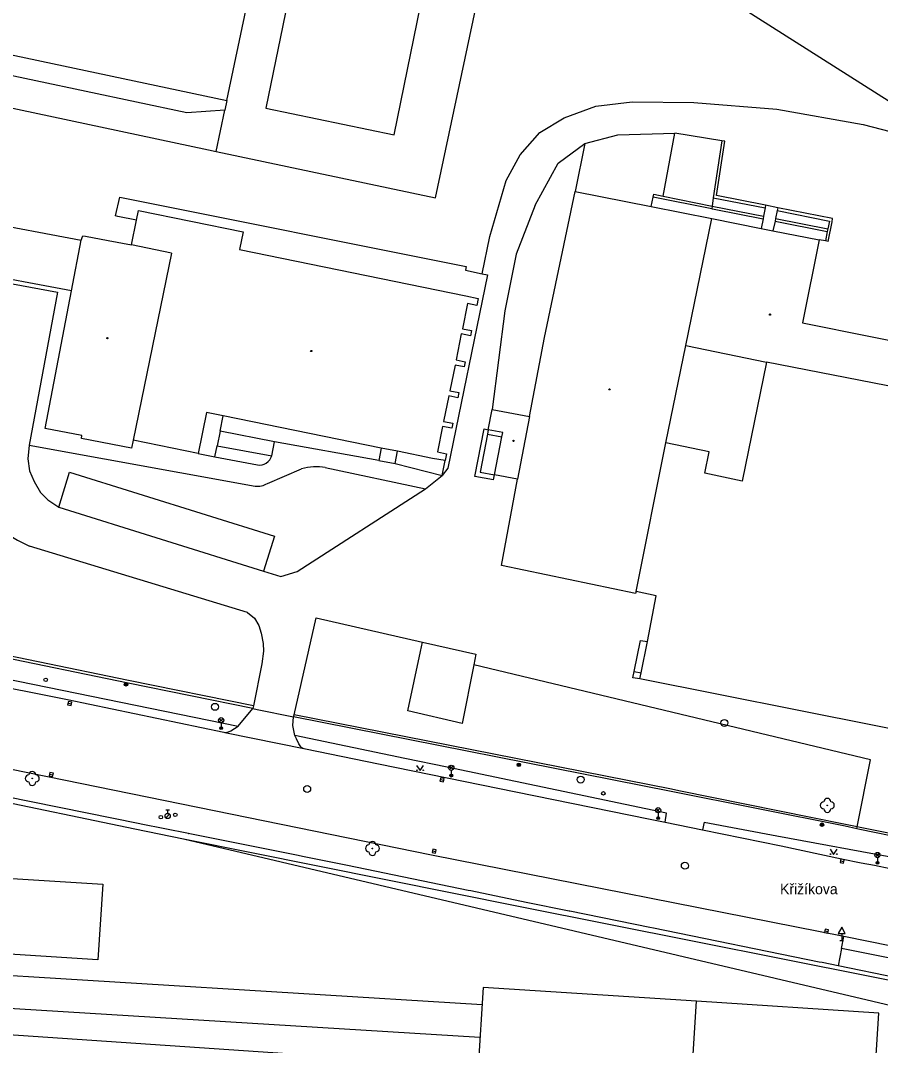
# Model space of a CAD drawing. Extents: x -598233 to -596890, y -1157848 to -1156431.
# Drawn here: x -597625.8 to -597502.6, y -1157653.8 to -1157507 of the extents above; entities that cross this region are included whole.
import ezdxf

# ---------------------------------------------------------------- set-up
doc = ezdxf.new("R2010")
doc.units = 0
for name, color, linetype in [('Level 10', 7, 'Continuous'), ('Level 11', 7, 'Continuous'), ('Level 13', 7, 'Continuous'), ('Level 22', 7, 'Continuous'), ('Level 25', 7, 'Continuous'), ('Level 27', 7, 'Continuous'), ('Level 28', 7, 'Continuous'), ('Level 33', 7, 'Continuous'), ('Level 34', 7, 'Continuous'), ('Level 36', 7, 'Continuous'), ('Level 39', 7, 'Continuous'), ('Level 49', 7, 'Continuous'), ('Level 5', 7, 'Continuous'), ('Level 51', 7, 'Continuous'), ('Level 7', 7, 'Continuous'), ('Level 8', 7, 'Continuous')]:
    doc.layers.add(name, color=color, linetype=linetype)

msp = doc.modelspace()

# ---------------------------------------------------------------- linework, layer by layer
at = {"layer": 'Level 10'}
for points in [[(-597633.4, -1157543.48), (-597620.4699, -1157545.9099)], [(-597620.4699, -1157545.9099), (-597624.53, -1157567.8)], [(-597624.53, -1157567.8), (-597624.72, -1157569.78), (-597624.49, -1157571.47), (-597623.82, -1157572.99), (-597622.9, -1157574.58), (-597621.87, -1157575.64), (-597620.3, -1157576.7), (-597590.96, -1157585.84), (-597588.51, -1157586.6), (-597586.17, -1157585.9), (-597567.78, -1157574.05), (-597565.39, -1157572.13)], [(-597565.39, -1157572.13), (-597564.94, -1157570.01)], [(-597635.67, -1157571.81), (-597634.43, -1157573.64), (-597633.36, -1157575.03), (-597632.17, -1157576.55), (-597630.85, -1157577.96), (-597629.4099, -1157579.24), (-597627.86, -1157580.4), (-597626.2199, -1157581.4099), (-597624.5, -1157582.27)], [(-597593.27, -1157591.75), (-597624.5, -1157582.27)], [(-597593.27, -1157591.75), (-597592.26, -1157592.6), (-597591.63, -1157593.62), (-597591.3, -1157594.7199), (-597591, -1157596.19), (-597590.9699, -1157597.33), (-597591.2, -1157599.14), (-597592.43, -1157605.15)], [(-597586.6, -1157606.4099), (-597583.4099, -1157592.55), (-597568.21, -1157596.04)], [(-597671.31, -1157593.83), (-597619.03, -1157604.2199)], [(-597619.03, -1157604.2199), (-597596.67, -1157608.92)], [(-597621.93, -1157615.29), (-597674.27, -1157604.65)], [(-597594.61, -1157608.05), (-597592.5, -1157605.54)], [(-597592.43, -1157605.15), (-597592.5, -1157605.54)], [(-597586.4699, -1157609.38), (-597586.54, -1157609.14), (-597586.75, -1157607.93), (-597586.67, -1157606.7)], [(-597586.67, -1157606.7), (-597586.6, -1157606.4099)], [(-597596.53, -1157608.95), (-597595.98, -1157608.86), (-597595.64, -1157608.73), (-597594.61, -1157608.05)], [(-597596.67, -1157608.92), (-597596.53, -1157608.95)], [(-597585.61, -1157610.99), (-597585.93, -1157610.59), (-597586.26, -1157609.88), (-597586.4699, -1157609.38)], [(-597585.61, -1157610.99), (-597585.32, -1157611.18), (-597584.98, -1157611.31)], [(-597584.98, -1157611.31), (-597574.51, -1157613.44), (-597554.85, -1157617.46)], [(-597566.92, -1157626.51), (-597621.93, -1157615.29)], [(-597554.85, -1157617.46), (-597535.85, -1157621.33), (-597533.43, -1157621.81)], [(-597533.43, -1157621.81), (-597528.09, -1157622.92)], [(-597528.09, -1157622.92), (-597516.85, -1157625.2), (-597508.21, -1157627.05)], [(-597507.85, -1157638.1599), (-597566.92, -1157626.51)], [(-597508.21, -1157627.05), (-597505.35, -1157627.62)], [(-597505.35, -1157627.62), (-597503.4819, -1157627.9801), (-597501.2, -1157628.42)], [(-597491.12, -1157641.55), (-597507.85, -1157638.1599)]]:
    msp.add_lwpolyline(points, dxfattribs=at)
at = {"layer": 'Level 11'}
for points in [[(-597597.75, -1157525.73), (-597566.34, -1157532.39), (-597552.94, -1157469.18), (-597580.35, -1157463.36), (-597584.95, -1157462.39), (-597589.3, -1157484.57), (-597590.46, -1157490.48), (-597591.27, -1157494.59), (-597591.84, -1157497.49)], [(-597638.81, -1157517.02), (-597598.85, -1157525.5), (-597597.75, -1157525.73), (-597596.5, -1157519.84), (-597601.97, -1157520.22), (-597638.03, -1157512.58)], [(-597596.21, -1157518.42), (-597596.5, -1157519.84)], [(-597533.75, -1157532.13), (-597532.07, -1157523.14)], [(-597560.69, -1157572.27), (-597559.37, -1157565.48)], [(-597558.9099, -1157566.23), (-597559.95, -1157571.65)], [(-597559.37, -1157565.48), (-597558.79, -1157565.6)], [(-597558.79, -1157565.6), (-597558.9099, -1157566.23)], [(-597558.9099, -1157566.23), (-597556.82, -1157566.62)], [(-597574.47, -1157570.01), (-597589.4, -1157567.34)], [(-597624.53, -1157567.8), (-597592.17, -1157573.68)], [(-597597.93, -1157569.45), (-597591.85, -1157570.64)], [(-597572.12, -1157570.44), (-597565.39, -1157572.13)], [(-597620.3, -1157576.7), (-597618.74, -1157571.69), (-597589.4, -1157580.82), (-597590.96, -1157585.84)], [(-597590.42, -1157573.29), (-597585.53, -1157571.18)], [(-597582.12, -1157571.02), (-597567.78, -1157574.05)], [(-597559.95, -1157571.65), (-597557.88, -1157572.03)], [(-597558.03, -1157572.76), (-597557.88, -1157572.03)], [(-597558.03, -1157572.76), (-597560.69, -1157572.27)], [(-597676.36, -1157591.33), (-597594.61, -1157608.05)], [(-597537.87, -1157600.24), (-597536.96, -1157595.77)], [(-597536.96, -1157595.77), (-597535.98, -1157595.93)], [(-597504.05, -1157612.89), (-597560.85, -1157599.26)], [(-597538.07, -1157601.12), (-597537.87, -1157600.24)], [(-597537.05, -1157601.25), (-597538.07, -1157601.12)], [(-597537.87, -1157600.24), (-597536.89, -1157600.43)], [(-597491.96, -1157645.79), (-597508.68, -1157642.39), (-597510.96, -1157641.92), (-597511.41, -1157641.83), (-597535.12, -1157637), (-597535.65, -1157636.89), (-597547.1, -1157634.56), (-597547.18, -1157634.54), (-597553.34, -1157633.29), (-597561.28, -1157631.65), (-597561.64, -1157631.58), (-597578.94, -1157628), (-597585.37, -1157626.71), (-597586, -1157626.59), (-597601.76, -1157623.43), (-597601.71, -1157623.44), (-597608.51, -1157622.07), (-597608.71, -1157622.03), (-597631.86, -1157617.38), (-597642.86, -1157615.26), (-597643.46, -1157615.15), (-597647.47, -1157614.38), (-597647.55, -1157614.36), (-597675.48, -1157609)], [(-597596.53, -1157608.95), (-597584.98, -1157611.31)], [(-597564.69, -1157613.93), (-597570.7163, -1157612.671), (-597586.4699, -1157609.38)], [(-597505.95, -1157622.46), (-597504.05, -1157612.89)], [(-597533.43, -1157621.81), (-597533.27, -1157620.51), (-597564.69, -1157613.93)], [(-597527.84, -1157621.82), (-597528.09, -1157622.92)], [(-597527.84, -1157621.82), (-597517.4342, -1157623.7531), (-597499.85, -1157627.02)], [(-597506.01, -1157622.73), (-597505.95, -1157622.46)], [(-597602.44, -1157624.18), (-597475.74, -1157654.04)], [(-597461.03, -1157650.48), (-597463.1, -1157650.13), (-597465.56, -1157648.5), (-597483.03, -1157644.94), (-597491.4609, -1157643.2511), (-597508.19, -1157639.9), (-597507.85, -1157638.1599)], [(-597508.19, -1157639.9), (-597508.68, -1157642.39)]]:
    msp.add_lwpolyline(points, dxfattribs=at)
for centre, radius, start, end in [((-597591.5963, -1157568.7548), 1.9022, 262.33607, 342.71371), ((-597583.4727, -1157578.6081), 7.7078, 79.892254, 105.480536), ((-597591.875, -1157570.8824), 2.8131, 263.980932, 301.146006)]:
    msp.add_arc(centre, radius, start, end, dxfattribs=at)
at = {"layer": 'Level 13'}
for points in [[(-597559.6599, -1157647.95), (-597822.77, -1157631.75)], [(-597559.9699, -1157652.64), (-597735.9699, -1157641.81)]]:
    msp.add_lwpolyline(points, dxfattribs=at)
at = {"layer": 'Level 22'}
for centre in [(-597624.09, -1157615.53), (-597510.2199, -1157619.39), (-597575.38, -1157625.56)]:
    msp.add_circle(centre, 0.05, dxfattribs=at)
for centre, start, end in [((-597624.09, -1157615.03), 0, 180), ((-597624.59, -1157615.53), 90, 270), ((-597624.09, -1157616.03), 180, 0), ((-597623.59, -1157615.53), 270, 90), ((-597510.7199, -1157619.39), 90, 270), ((-597510.2199, -1157618.89), 0, 180), ((-597509.7199, -1157619.39), 270, 90), ((-597510.2199, -1157619.89), 180, 0), ((-597575.38, -1157625.06), 0, 180), ((-597575.88, -1157625.56), 90, 270), ((-597575.38, -1157626.06), 180, 0), ((-597574.88, -1157625.56), 270, 90)]:
    msp.add_arc(centre, 0.5, start, end, dxfattribs=at)
at = {"layer": 'Level 25'}
for centre, radius in [((-597610.68, -1157602.06), 0.25), ((-597610.68, -1157602.06), 0.2), ((-597610.68, -1157602.06), 0.15), ((-597610.68, -1157602.06), 0.1), ((-597610.68, -1157602.06), 0.05), ((-597554.4, -1157613.58), 0.25), ((-597554.4, -1157613.58), 0.2), ((-597554.4, -1157613.58), 0.15), ((-597554.4, -1157613.58), 0.1), ((-597554.4, -1157613.58), 0.05), ((-597510.99, -1157622.1599), 0.25), ((-597510.99, -1157622.1599), 0.2), ((-597510.99, -1157622.1599), 0.15), ((-597510.99, -1157622.1599), 0.1), ((-597510.99, -1157622.1599), 0.05)]:
    msp.add_circle(centre, radius, dxfattribs=at)
at = {"layer": 'Level 27'}
for p, q in [((-597618.9747, -1157604.7387), (-597618.4853, -1157604.8413)), ((-597621.6147, -1157614.9287), (-597621.1253, -1157615.0313)), ((-597565.6448, -1157615.6792), (-597565.1552, -1157615.7808)), ((-597566.7848, -1157625.8992), (-597566.2952, -1157626.0008)), ((-597508.3244, -1157627.3172), (-597507.8356, -1157627.4228)), ((-597510.5744, -1157637.3472), (-597510.0856, -1157637.4528))]:
    msp.add_line(p, q, dxfattribs=at)
for points in [[(-597619.026, -1157604.9833), (-597618.5367, -1157605.086), (-597618.434, -1157604.5967), (-597618.9233, -1157604.494)], [(-597621.666, -1157615.1733), (-597621.1767, -1157615.276), (-597621.074, -1157614.7867), (-597621.5633, -1157614.684)], [(-597565.6956, -1157615.924), (-597565.206, -1157616.0256), (-597565.1044, -1157615.536), (-597565.594, -1157615.4344)], [(-597566.8356, -1157626.144), (-597566.346, -1157626.2456), (-597566.2444, -1157625.756), (-597566.734, -1157625.6544)], [(-597508.3772, -1157627.5616), (-597507.8884, -1157627.6672), (-597507.7828, -1157627.1784), (-597508.2716, -1157627.0728)], [(-597510.6272, -1157637.5916), (-597510.1384, -1157637.6972), (-597510.0328, -1157637.2084), (-597510.5216, -1157637.1028)]]:
    msp.add_lwpolyline(points, close=True, dxfattribs=at)
for centre in [(-597597.92, -1157605.28), (-597524.96, -1157607.59), (-597545.55, -1157615.7), (-597584.7199, -1157617.04), (-597530.62, -1157628.04)]:
    msp.add_circle(centre, 0.5, dxfattribs=at)
at = {"layer": 'Level 28'}
for p, q in [((-597604.95, -1157620.0349), (-597604.45, -1157620.0349)), ((-597604.7, -1157620.5349), (-597604.7, -1157620.0349)), ((-597604.958, -1157621.1819), (-597604.428, -1157620.6519))]:
    msp.add_line(p, q, dxfattribs=at)
for centre, radius in [((-597622.17, -1157601.4099), 0.25), ((-597542.3, -1157617.67), 0.25), ((-597604.7, -1157620.9099), 0.375), ((-597603.61, -1157620.74), 0.25), ((-597605.68, -1157621.09), 0.25)]:
    msp.add_circle(centre, radius, dxfattribs=at)
at = {"layer": 'Level 33'}
for p, q in [((-597597.305, -1157607.47), (-597596.775, -1157606.94)), ((-597597.305, -1157606.94), (-597596.775, -1157607.47)), ((-597597.04, -1157607.58), (-597597.04, -1157608.33)), ((-597564.345, -1157614.27), (-597563.815, -1157613.74)), ((-597564.345, -1157613.74), (-597563.815, -1157614.27)), ((-597564.08, -1157614.38), (-597564.08, -1157615.13)), ((-597534.715, -1157620.35), (-597534.185, -1157619.82)), ((-597534.715, -1157619.82), (-597534.185, -1157620.35)), ((-597534.45, -1157620.46), (-597534.45, -1157621.21)), ((-597503.305, -1157626.77), (-597502.775, -1157626.24)), ((-597503.305, -1157626.24), (-597502.775, -1157626.77)), ((-597503.04, -1157626.88), (-597503.04, -1157627.63))]:
    msp.add_line(p, q, dxfattribs=at)
for centre, radius in [((-597597.04, -1157607.205), 0.375), ((-597597.04, -1157608.33), 0.2), ((-597597.04, -1157608.33), 0.1445), ((-597597.04, -1157608.33), 0.0876), ((-597564.08, -1157614.005), 0.375), ((-597564.08, -1157615.13), 0.2), ((-597564.08, -1157615.13), 0.1445), ((-597564.08, -1157615.13), 0.0876), ((-597534.45, -1157620.085), 0.375), ((-597534.45, -1157621.21), 0.2), ((-597534.45, -1157621.21), 0.1445), ((-597534.45, -1157621.21), 0.0876), ((-597503.04, -1157626.505), 0.375), ((-597503.04, -1157627.63), 0.2), ((-597503.04, -1157627.63), 0.1445), ((-597503.04, -1157627.63), 0.0876)]:
    msp.add_circle(centre, radius, dxfattribs=at)
at = {"layer": 'Level 34'}
for p, q in [((-597508.1599, -1157637.722), (-597508.1599, -1157638.74)), ((-597508.4099, -1157638.74), (-597507.9099, -1157638.74))]:
    msp.add_line(p, q, dxfattribs=at)
msp.add_lwpolyline([(-597508.6599, -1157637.722), (-597507.6599, -1157637.722), (-597508.1599, -1157636.856)], close=True, dxfattribs=at)
at = {"layer": 'Level 36'}
for points in [[(-597569.04, -1157613.67), (-597568.54, -1157614.42), (-597568.04, -1157613.67)], [(-597509.81, -1157625.67), (-597509.31, -1157626.42), (-597508.81, -1157625.67)]]:
    msp.add_lwpolyline(points, dxfattribs=at)
for centre in [(-597568.9902, -1157614.3698), (-597568.0908, -1157614.3698), (-597509.7602, -1157626.3698), (-597508.8608, -1157626.3698)]:
    msp.add_circle(centre, 0.05, dxfattribs=at)
at = {"layer": 'Level 39'}
for centre, radius in [((-597518.43, -1157549.1), 0.09), ((-597518.43, -1157549.1), 0.0398), ((-597613.34, -1157552.4699), 0.09), ((-597613.34, -1157552.4699), 0.0398), ((-597584.13, -1157554.32), 0.09), ((-597584.13, -1157554.32), 0.0398), ((-597541.42, -1157559.81), 0.09), ((-597541.42, -1157559.81), 0.0398), ((-597555.17, -1157567.2), 0.09), ((-597555.17, -1157567.2), 0.0398)]:
    msp.add_circle(centre, radius, dxfattribs=at)
at = {"layer": 'Level 5'}
for points in [[(-597596.21, -1157518.42), (-597592.39, -1157500.29)], [(-597650.02, -1157507.01), (-597596.21, -1157518.42)], [(-597550.7199, -1157552.39), (-597546.34, -1157531.48)], [(-597546.34, -1157531.48), (-597535.44, -1157533.62)], [(-597535.44, -1157533.62), (-597526.76, -1157535.36)], [(-597609.1599, -1157535.56), (-597608.87, -1157534.19)], [(-597608.87, -1157534.19), (-597593.9, -1157537.26)], [(-597530.5, -1157553.55), (-597526.76, -1157535.36)], [(-597526.76, -1157535.36), (-597519.67, -1157536.78)], [(-597631.81, -1157535.67), (-597617.07, -1157538.43)], [(-597609.89, -1157539.1), (-597609.1599, -1157535.56)], [(-597519.67, -1157536.78), (-597518, -1157537.09)], [(-597617.07, -1157538.43), (-597616.86, -1157537.83)], [(-597616.86, -1157537.83), (-597616.48, -1157537.88)], [(-597616.48, -1157537.88), (-597613.24, -1157538.4699)], [(-597593.9, -1157537.26), (-597594.4, -1157539.79)], [(-597518, -1157537.09), (-597511.37, -1157538.38)], [(-597618.4699, -1157545.69), (-597617.07, -1157538.43)], [(-597613.24, -1157538.4699), (-597609.89, -1157539.1)], [(-597604.14, -1157540.31), (-597609.89, -1157539.1)], [(-597594.4, -1157539.79), (-597562, -1157546.4099)], [(-597511.37, -1157538.38), (-597513.76, -1157550.29)], [(-597604.14, -1157540.31), (-597609.6599, -1157567.11)], [(-597618.4699, -1157545.69), (-597633.27, -1157542.95)], [(-597622.27, -1157565.4099), (-597618.4699, -1157545.69)], [(-597562, -1157546.4099), (-597560.24, -1157546.8)], [(-597560.24, -1157546.8), (-597560.43, -1157547.79)], [(-597561.76, -1157547.52), (-597562.49, -1157551.15)], [(-597560.43, -1157547.79), (-597561.76, -1157547.52)], [(-597562.49, -1157551.15), (-597561.19, -1157551.4)], [(-597561.19, -1157551.4), (-597561.34, -1157552.13)], [(-597513.76, -1157550.29), (-597493.81, -1157554.31)], [(-597562.64, -1157551.88), (-597563.4, -1157555.6)], [(-597561.34, -1157552.13), (-597562.64, -1157551.88)], [(-597552.87, -1157563.7), (-597550.7199, -1157552.39)], [(-597533.36, -1157567.4699), (-597530.5, -1157553.55)], [(-597530.5, -1157553.55), (-597518.93, -1157555.92)], [(-597563.4, -1157555.6), (-597562.09, -1157555.86)], [(-597562.09, -1157555.86), (-597562.24, -1157556.59)], [(-597518.93, -1157555.92), (-597522.43, -1157572.96)], [(-597461.63, -1157567.07), (-597518.93, -1157555.92)], [(-597563.54, -1157556.33), (-597564.29, -1157560)], [(-597562.24, -1157556.59), (-597563.54, -1157556.33)], [(-597564.29, -1157560), (-597562.98, -1157560.26)], [(-597562.98, -1157560.26), (-597563.13, -1157561.01)], [(-597564.44, -1157560.75), (-597565.18, -1157564.39)], [(-597563.13, -1157561.01), (-597564.44, -1157560.75)], [(-597599.14, -1157563.12), (-597600.32, -1157568.98)], [(-597596.76, -1157563.6), (-597599.14, -1157563.12)], [(-597558.79, -1157565.6), (-597558.23, -1157562.69)], [(-597558.23, -1157562.69), (-597552.87, -1157563.7)], [(-597574.12, -1157568.21), (-597596.76, -1157563.6)], [(-597565.18, -1157564.39), (-597563.86, -1157564.65)], [(-597563.86, -1157564.65), (-597564.01, -1157565.38)], [(-597552.87, -1157563.7), (-597554.58, -1157572.65)], [(-597616.99, -1157566.44), (-597622.27, -1157565.4099)], [(-597565.33, -1157565.12), (-597566.07, -1157568.77)], [(-597564.01, -1157565.38), (-597565.33, -1157565.12)], [(-597556.7, -1157566.01), (-597558.79, -1157565.6)], [(-597556.82, -1157566.62), (-597556.7, -1157566.01)], [(-597617.03, -1157566.86), (-597616.99, -1157566.44)], [(-597609.89, -1157568.2199), (-597617.03, -1157566.86)], [(-597609.6599, -1157567.11), (-597609.89, -1157568.2199)], [(-597600.32, -1157568.98), (-597609.6599, -1157567.11)], [(-597557.88, -1157572.03), (-597556.82, -1157566.62)], [(-597537.61, -1157588.76), (-597533.36, -1157567.4699)], [(-597527.13, -1157568.78), (-597533.36, -1157567.4699)], [(-597571.77, -1157568.68), (-597574.12, -1157568.21)], [(-597566.78, -1157569.7), (-597571.77, -1157568.68)], [(-597566.07, -1157568.77), (-597564.75, -1157569.04)], [(-597564.75, -1157569.04), (-597564.94, -1157570.01)], [(-597527.75, -1157571.83), (-597527.13, -1157568.78)], [(-597564.94, -1157570.01), (-597566.78, -1157569.7)], [(-597554.58, -1157572.65), (-597557.88, -1157572.03)], [(-597522.43, -1157572.96), (-597527.75, -1157571.83)], [(-597556.88, -1157585.03), (-597554.58, -1157572.65)], [(-597537.67, -1157589.06), (-597556.88, -1157585.03)], [(-597537.61, -1157588.76), (-597537.67, -1157589.06)], [(-597534.71, -1157589.39), (-597537.61, -1157588.76)], [(-597535.98, -1157595.93), (-597534.71, -1157589.39)], [(-597536.89, -1157600.43), (-597535.98, -1157595.93)], [(-597537.05, -1157601.25), (-597536.89, -1157600.43)], [(-597469.89, -1157614.7), (-597502.53, -1157608.16), (-597503.03, -1157608.06), (-597537.05, -1157601.25)], [(-597639.27, -1157629.08), (-597614.01, -1157630.68)], [(-597614.01, -1157630.68), (-597614.69, -1157641.51)], [(-597614.69, -1157641.51), (-597655.56, -1157638.9099)], [(-597559.5, -1157645.46), (-597560.24, -1157656.84)], [(-597528.9699, -1157647.44), (-597559.5, -1157645.46)], [(-597535.27, -1157747.99), (-597528.9699, -1157647.44)], [(-597560.24, -1157656.84), (-597649.2199, -1157650.78)]]:
    msp.add_lwpolyline(points, dxfattribs=at)
at = {"layer": 'Level 51'}
for points in [[(-597572.28, -1157523.35), (-597563.26, -1157479.35)], [(-597582.64, -1157480.48), (-597590.64, -1157519.55)], [(-597483.9, -1157529.65), (-597545.4699, -1157490.57)], [(-597547.9, -1157520.9), (-597543.38, -1157519.25)], [(-597543.38, -1157519.25), (-597538.1599, -1157518.62)], [(-597538.1599, -1157518.62), (-597529.33, -1157518.7199)], [(-597529.33, -1157518.7199), (-597517.45, -1157519.68)], [(-597590.64, -1157519.55), (-597572.28, -1157523.35)], [(-597517.45, -1157519.68), (-597505.1, -1157521.87)], [(-597551.4, -1157523.03), (-597547.9, -1157520.9)], [(-597505.1, -1157521.87), (-597494.75, -1157524.56)], [(-597554.23, -1157526.21), (-597551.4, -1157523.03)], [(-597544.9699, -1157524.62), (-597540.2199, -1157523.37)], [(-597540.2199, -1157523.37), (-597532.07, -1157523.14)], [(-597525.33, -1157524.21), (-597532.07, -1157523.14)], [(-597548.77, -1157527.4099), (-597544.9699, -1157524.62)], [(-597544.9699, -1157524.62), (-597546.34, -1157531.48)], [(-597525.33, -1157524.21), (-597526.55, -1157532.4)], [(-597526.11, -1157532.04), (-597524.9099, -1157524.27)], [(-597524.9099, -1157524.27), (-597525.33, -1157524.21)], [(-597556.21, -1157529.88), (-597554.23, -1157526.21)], [(-597552.07, -1157533.42), (-597548.77, -1157527.4099)], [(-597558.56, -1157537.92), (-597556.21, -1157529.88)], [(-597612.15, -1157534.9699), (-597611.57, -1157532.29)], [(-597611.57, -1157532.29), (-597561.94, -1157542.2)], [(-597535.44, -1157533.62), (-597535.17, -1157532.28)], [(-597535.17, -1157532.28), (-597535.09, -1157531.86)], [(-597526.78, -1157533.94), (-597535.17, -1157532.28)], [(-597535.09, -1157531.86), (-597533.75, -1157532.13), (-597526.73, -1157533.55)], [(-597526.55, -1157532.4), (-597526.73, -1157533.55)], [(-597526.55, -1157532.4), (-597519.12, -1157533.83)], [(-597519.05, -1157533.45), (-597526.11, -1157532.04)], [(-597552.07, -1157533.42), (-597554.78, -1157540.4699)], [(-597526.73, -1157533.55), (-597526.78, -1157533.94)], [(-597526.73, -1157533.55), (-597519.34, -1157534.99)], [(-597519.12, -1157533.83), (-597519.34, -1157534.99)], [(-597519.05, -1157533.45), (-597519.12, -1157533.83)], [(-597517.3, -1157533.79), (-597519.05, -1157533.45)], [(-597517.3, -1157533.79), (-597517.38, -1157534.18)], [(-597509.46, -1157535.35), (-597517.3, -1157533.79)], [(-597611.83, -1157535.03), (-597612.15, -1157534.9699)], [(-597609.1599, -1157535.56), (-597611.83, -1157535.03)], [(-597526.78, -1157533.94), (-597526.44, -1157534.01)], [(-597526.44, -1157534.01), (-597519.4099, -1157535.4099)], [(-597519.34, -1157534.99), (-597519.4099, -1157535.4099)], [(-597517.62, -1157535.33), (-597517.71, -1157535.73)], [(-597517.38, -1157534.18), (-597517.62, -1157535.33)], [(-597517.62, -1157535.33), (-597510.14, -1157536.81)], [(-597517.38, -1157534.18), (-597509.92, -1157535.71)], [(-597509.52, -1157535.8), (-597509.46, -1157535.35)], [(-597519.4099, -1157535.4099), (-597519.67, -1157536.78)], [(-597517.71, -1157535.73), (-597518, -1157537.09)], [(-597517.71, -1157535.73), (-597510.2199, -1157537.21)], [(-597510.14, -1157536.81), (-597510.2199, -1157537.21)], [(-597509.92, -1157535.71), (-597510.14, -1157536.81)], [(-597510.1, -1157538.61), (-597509.52, -1157535.8)], [(-597559.64, -1157543.24), (-597558.56, -1157537.92)], [(-597510.2199, -1157537.21), (-597510.48, -1157538.56)], [(-597510.48, -1157538.56), (-597511.37, -1157538.38)], [(-597510.1, -1157538.61), (-597510.48, -1157538.56)], [(-597554.78, -1157540.4699), (-597556.4099, -1157548.56)], [(-597561.94, -1157542.2), (-597562.04, -1157542.75)], [(-597558.87, -1157543.4099), (-597564.58, -1157571.1)], [(-597562.04, -1157542.75), (-597559.64, -1157543.24)], [(-597559.64, -1157543.24), (-597558.87, -1157543.4099)], [(-597556.4099, -1157548.56), (-597558.23, -1157562.69)], [(-597597.2, -1157565.82), (-597596.76, -1157563.6)], [(-597597.2, -1157565.82), (-597597.61, -1157567.9)], [(-597589.4, -1157567.34), (-597597.2, -1157565.82)], [(-597589.78, -1157569.32), (-597589.4, -1157567.34)], [(-597600.32, -1157568.98), (-597597.93, -1157569.45)], [(-597597.93, -1157569.45), (-597597.61, -1157567.9)], [(-597597.61, -1157567.9), (-597589.78, -1157569.32)], [(-597574.12, -1157568.21), (-597574.4699, -1157570.01)], [(-597572.12, -1157570.44), (-597571.77, -1157568.68)], [(-597574.4699, -1157570.01), (-597572.12, -1157570.44)], [(-597564.58, -1157571.1), (-597565.39, -1157572.13)], [(-597502.82, -1157649.14), (-597528.9699, -1157647.44)], [(-597504.32, -1157672.4), (-597502.82, -1157649.14)]]:
    msp.add_lwpolyline(points, dxfattribs=at)
at = {"layer": 'Level 7'}
for points in [[(-597610.38, -1157601.88), (-597649.27, -1157593.89)], [(-597610.3, -1157601.49), (-597649.19, -1157593.49)], [(-597568.49, -1157597.35), (-597568.21, -1157596.04)], [(-597568.21, -1157596.04), (-597560.54, -1157597.7199)], [(-597570.31, -1157605.86), (-597568.49, -1157597.35)], [(-597560.54, -1157597.7199), (-597560.85, -1157599.26)], [(-597560.85, -1157599.26), (-597562.52, -1157607.69)], [(-597592.5, -1157605.54), (-597610.38, -1157601.88)], [(-597592.43, -1157605.15), (-597610.3, -1157601.49)], [(-597562.52, -1157607.69), (-597570.31, -1157605.86)], [(-597532.6, -1157617.39), (-597586.67, -1157606.7)], [(-597532.54, -1157617.09), (-597586.6, -1157606.4099)], [(-597675.48, -1157609), (-597609.42, -1157622.75)], [(-597506.01, -1157622.73), (-597507.64, -1157622.36), (-597532.6, -1157617.39)], [(-597531.49, -1157617.3), (-597532.54, -1157617.09)], [(-597505.95, -1157622.46), (-597507.6, -1157622.13), (-597531.49, -1157617.3)], [(-597609.42, -1157622.75), (-597602.44, -1157624.18)], [(-597499.01, -1157624.17), (-597505.58, -1157622.83), (-597506.01, -1157622.73)], [(-597487.73, -1157626.11), (-597505.53, -1157622.54), (-597505.95, -1157622.46)], [(-597602.44, -1157624.18), (-597554.19, -1157633.89)], [(-597554.19, -1157633.89), (-597491.4256, -1157646.3942), (-597474.28, -1157649.81)]]:
    msp.add_lwpolyline(points, dxfattribs=at)
at = {"layer": 'Level 8'}
msp.add_lwpolyline([(-597592.5, -1157605.54), (-597591.8906, -1157605.6612), (-597586.67, -1157606.7)], dxfattribs=at)

# ---------------------------------------------------------------- texts
at = {"layer": 'Level 49'}
msp.add_text('Křižíkova', height=1.5, dxfattribs=at).set_placement((-597516.99, -1157632.12))

doc.saveas('drawing.dxf')
